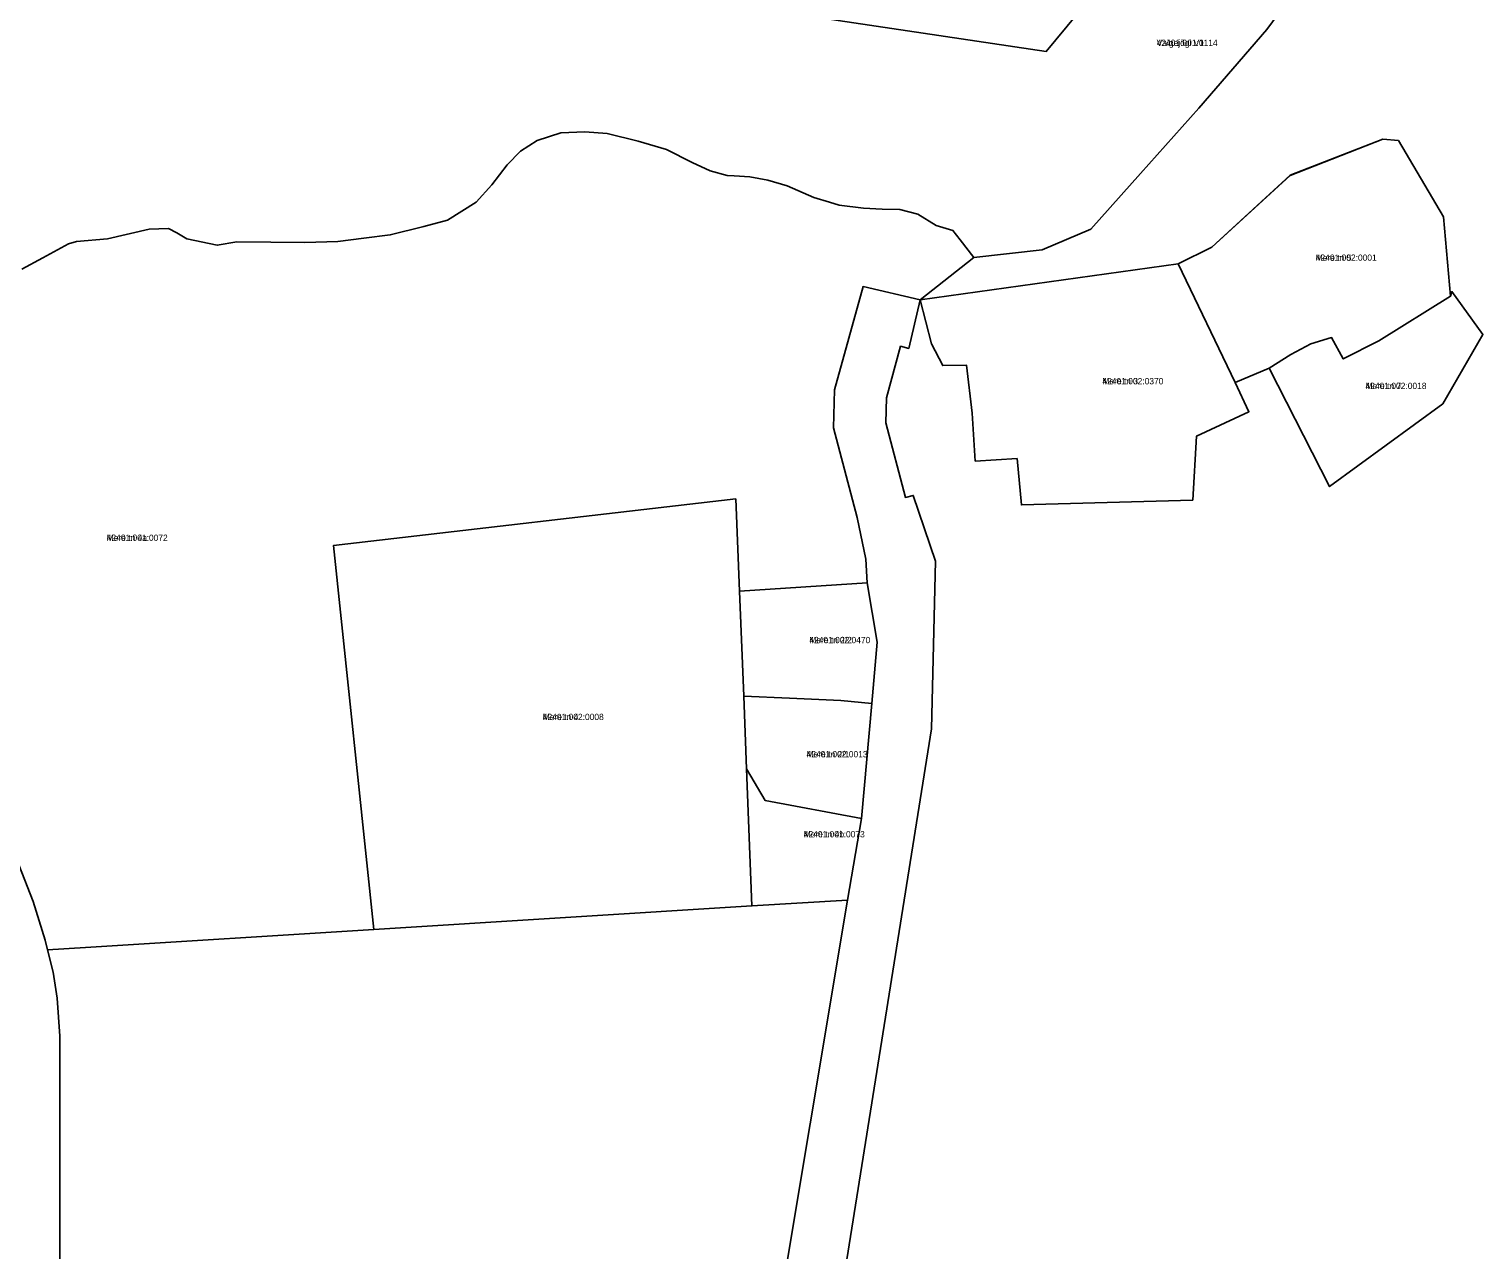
# Model space of a CAD drawing. Extents: x 595979 to 597983, y 6604231 to 6607350.
# Drawn here: x 596481.3 to 596827.1, y 6606049.7 to 6606340.2 of the extents above; entities that cross this region are included whole.
import ezdxf

# ---------------------------------------------------------------- set-up
doc = ezdxf.new("R2010")
doc.units = 0
for name, color, linetype in [('L_AADRESS', 7, 'Continuous'), ('PIIR', 7, 'Continuous'), ('TUNNUS', 7, 'Continuous')]:
    doc.layers.add(name, color=color, linetype=linetype)

msp = doc.modelspace()

# ---------------------------------------------------------------- linework, layer by layer
at = {"layer": 'PIIR'}
for points in [[(596737.8, 6606352.55), (596723.23, 6606334.88), (596484.87, 6606370.45)], [(596484.87, 6606370.45), (596723.23, 6606334.88), (596737.8, 6606352.55)], [(596788.28, 6606357.27), (596775.7, 6606340.13), (596759.54, 6606321.38), (596745.69, 6606305.87), (596733.86, 6606292.56), (596722.23, 6606287.63), (596705.99, 6606285.87), (596702.76, 6606290.01), (596701.06, 6606292.25), (596697.04, 6606293.48), (596692.71, 6606296.12), (596688.4, 6606297.29), (596684.21, 6606297.31), (596679.74, 6606297.56), (596673.96, 6606298.3), (596671.65, 6606299), (596667.97, 6606300.11), (596661.64, 6606302.86), (596656.98, 6606304.28), (596652.71, 6606305.01), (596648.99, 6606305.24), (596647.36, 6606305.34), (596643.33, 6606306.44), (596639.01, 6606308.48), (596632.91, 6606311.52), (596626.15, 6606313.51), (596618.79, 6606315.38), (596613.47, 6606315.73), (596607.75, 6606315.55), (596602.13, 6606313.65), (596598.17, 6606311.17), (596595.02, 6606307.91), (596591.35, 6606303.14), (596587.64, 6606299.02), (596580.85, 6606294.74), (596575.23, 6606293.24), (596567.2, 6606291.22), (596560.92, 6606290.41), (596554.71, 6606289.66), (596546.89, 6606289.43), (596530.69, 6606289.53), (596526.06, 6606288.74), (596518.86, 6606290.29), (596516.42, 6606291.74), (596514.5, 6606292.75), (596509.88, 6606292.56), (596499.93, 6606290.27), (596492.57, 6606289.62), (596490.68, 6606289.09), (596484.62, 6606285.8), (596479.62, 6606283.09)], [(596664.52, 6605976.79), (596695.91, 6606173.63), (596696.92, 6606213.56), (596691.59, 6606229.22), (596689.75, 6606228.73), (596685.07, 6606246.49), (596685.22, 6606252.44), (596688.61, 6606264.73), (596690.54, 6606264.2), (596693.28, 6606275.73), (596695.94, 6606265.3), (596698.64, 6606260.1), (596704.26, 6606260.23), (596705.59, 6606248.82), (596706.35, 6606237.38), (596716.32, 6606237.98), (596717.34, 6606226.96), (596758.08, 6606228.11), (596758.96, 6606243.31), (596771.45, 6606249.13), (596768.15, 6606256.08), (596776.24, 6606259.52), (596790.61, 6606231.34), (596817.54, 6606251.04), (596827.1, 6606267.49), (596819.74, 6606277.71), (596819.39, 6606276.67), (596817.75, 6606295.55), (596807.01, 6606313.69), (596803.3, 6606314.02), (596781.28, 6606305.36), (596762.64, 6606288.33), (596754.61, 6606284.35), (596693.24, 6606275.74), (596705.99, 6606285.87), (596722.23, 6606287.63), (596733.86, 6606292.56), (596745.69, 6606305.87), (596759.54, 6606321.38), (596775.7, 6606340.13), (596788.28, 6606357.27)], [(596479.62, 6606283.09), (596484.62, 6606285.8), (596490.68, 6606289.09), (596492.57, 6606289.62), (596499.93, 6606290.27), (596509.88, 6606292.56), (596514.5, 6606292.75), (596516.42, 6606291.74), (596518.86, 6606290.29), (596526.06, 6606288.74), (596530.69, 6606289.53), (596546.89, 6606289.43), (596554.71, 6606289.66), (596560.92, 6606290.41), (596567.2, 6606291.22), (596575.23, 6606293.24), (596580.85, 6606294.74), (596587.64, 6606299.02), (596591.35, 6606303.14), (596595.02, 6606307.91), (596598.17, 6606311.17), (596602.13, 6606313.65), (596607.75, 6606315.55), (596613.47, 6606315.73), (596618.79, 6606315.38), (596626.15, 6606313.51), (596632.91, 6606311.52), (596639.01, 6606308.48), (596643.33, 6606306.44), (596647.36, 6606305.34), (596648.99, 6606305.24), (596652.71, 6606305.01), (596656.98, 6606304.28), (596661.64, 6606302.86), (596667.97, 6606300.11), (596671.65, 6606299), (596673.96, 6606298.3), (596679.74, 6606297.56), (596684.21, 6606297.31), (596688.4, 6606297.29), (596692.71, 6606296.12), (596697.04, 6606293.48), (596701.06, 6606292.25), (596702.76, 6606290.01), (596705.99, 6606285.87), (596693.24, 6606275.74), (596679.66, 6606278.93), (596672.85, 6606254.31), (596672.64, 6606245.27), (596678.25, 6606223.94), (596680.32, 6606214.05), (596680.64, 6606208.39), (596650.26, 6606206.44), (596649.4, 6606228.39), (596553.74, 6606217.31), (596563.33, 6606125.94), (596494.7, 6606121.64), (596485.68, 6606121.08), (596485.11, 6606123.37), (596482.25, 6606132.58), (596478.91, 6606141.31)], [(596649.26, 6605972.7), (596676, 6606132.91), (596679.28, 6606152.32), (596681.78, 6606179.72), (596683.04, 6606194.31), (596680.64, 6606208.39), (596680.32, 6606214.05), (596678.25, 6606223.94), (596672.64, 6606245.27), (596672.85, 6606254.31), (596679.66, 6606278.93), (596693.24, 6606275.74), (596690.54, 6606264.2), (596688.61, 6606264.73), (596685.22, 6606252.44), (596685.07, 6606246.49), (596689.75, 6606228.73), (596691.59, 6606229.22), (596696.92, 6606213.56), (596695.91, 6606173.63), (596664.52, 6605976.79)], [(596488.59, 6606015.77), (596488.6, 6606100.51), (596487.96, 6606109.56), (596487.01, 6606115.75), (596485.68, 6606121.08), (596494.7, 6606121.64), (596563.33, 6606125.94), (596653.24, 6606131.52), (596676, 6606132.91), (596649.26, 6605972.7)]]:
    msp.add_lwpolyline(points, dxfattribs=at)
for points in [[(596762.64, 6606288.33), (596781.27, 6606305.44), (596803.3, 6606314.02), (596807.01, 6606313.69), (596817.75, 6606295.55), (596819.39, 6606276.67), (596802.32, 6606266.02), (596793.87, 6606261.7), (596791.09, 6606266.78), (596786.2, 6606265.28), (596781.42, 6606262.76), (596776.24, 6606259.52), (596768.15, 6606256.08), (596754.61, 6606284.35)], [(596693.24, 6606275.74), (596754.61, 6606284.35), (596768.21, 6606256.06), (596771.45, 6606249.13), (596758.96, 6606243.31), (596758.08, 6606228.11), (596717.34, 6606226.96), (596716.32, 6606237.98), (596706.35, 6606237.38), (596705.59, 6606248.82), (596704.26, 6606260.23), (596698.64, 6606260.1), (596695.94, 6606265.3)], [(596819.74, 6606277.71), (596827.1, 6606267.49), (596817.54, 6606251.04), (596790.61, 6606231.34), (596776.24, 6606259.52), (596781.42, 6606262.76), (596786.2, 6606265.28), (596791.09, 6606266.78), (596793.87, 6606261.7), (596802.32, 6606266.02), (596819.39, 6606276.67)], [(596553.74, 6606217.31), (596649.4, 6606228.39), (596650.26, 6606206.44), (596651.28, 6606181.44), (596651.98, 6606164.15), (596653.24, 6606131.52), (596563.33, 6606125.94)], [(596650.26, 6606206.44), (596680.64, 6606208.39), (596683.04, 6606194.31), (596681.78, 6606179.72), (596674.35, 6606180.43), (596662.2, 6606180.99), (596651.28, 6606181.44)], [(596651.28, 6606181.44), (596662.2, 6606180.99), (596674.35, 6606180.43), (596681.78, 6606179.72), (596679.28, 6606152.32), (596656.38, 6606156.64), (596651.98, 6606164.15)], [(596676, 6606132.91), (596653.24, 6606131.52), (596651.98, 6606164.15), (596656.38, 6606156.64), (596679.28, 6606152.32)]]:
    msp.add_lwpolyline(points, close=True, dxfattribs=at)

# ---------------------------------------------------------------- texts
at = {"layer": 'L_AADRESS'}
for s, p in [('Valgejõgi V1', (596749.5, 6606336.18)), ('Mere tn 5', (596787.34, 6606285.05)), ('Mere tn 3', (596736.6, 6606255.66)), ('Mere tn 7', (596799.18, 6606254.53)), ('Mere tn 4a', (596499.78, 6606218.4)), ('Mere tn 2/2', (596666.89, 6606194.05)), ('Mere tn 4', (596603.49, 6606175.75)), ('Mere tn 2/1', (596666.24, 6606166.88)), ('Mere tn 4b', (596665.57, 6606147.83))]:
    msp.add_text(s, height=1.5, dxfattribs=at).set_placement(p)
at = {"layer": 'TUNNUS'}
for s, p in [('42401:001:0114', (596749.5, 6606336.18)), ('42401:002:0001', (596787.34, 6606285.05)), ('42401:002:0370', (596736.6, 6606255.66)), ('42401:002:0018', (596799.18, 6606254.53)), ('42401:001:0072', (596499.78, 6606218.4)), ('42401:002:0470', (596666.89, 6606194.05)), ('42401:002:0008', (596603.49, 6606175.75)), ('42401:002:0013', (596666.24, 6606166.88)), ('42401:001:0073', (596665.57, 6606147.83))]:
    msp.add_text(s, height=1.5, dxfattribs=at).set_placement(p)

doc.saveas('drawing.dxf')
